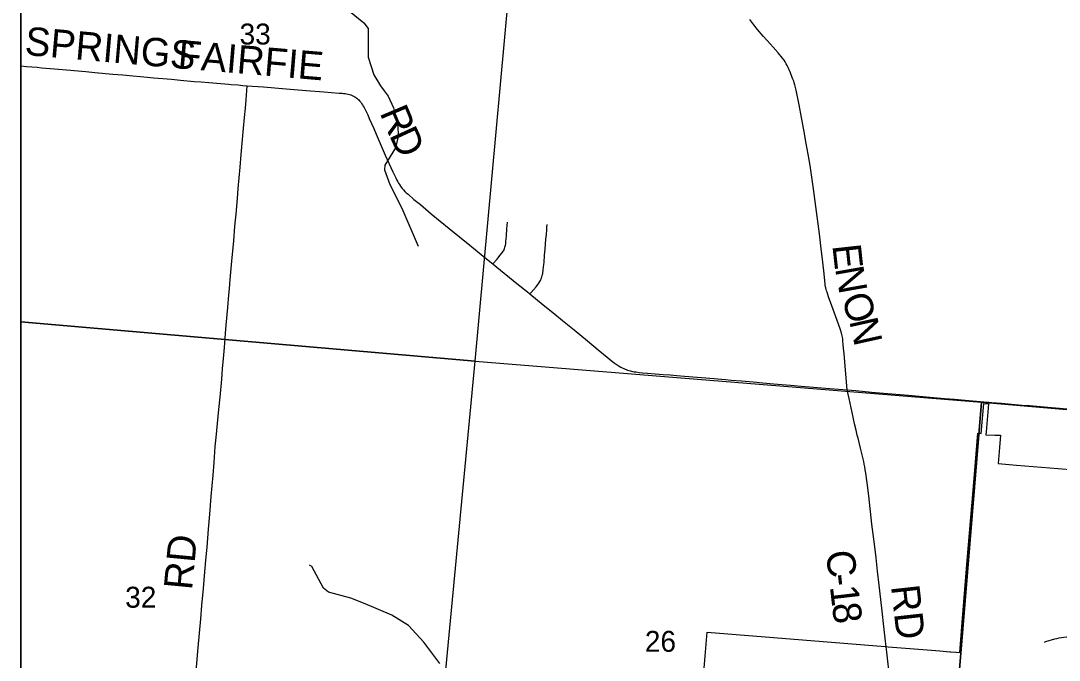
# Model space of a CAD drawing. Extents: x -1.4 to 35.4, y 0 to 22.
# Drawn here: x 17.06 to 19.136, y 17.381 to 18.66 of the extents above; entities that cross this region are included whole.
import ezdxf

# ---------------------------------------------------------------- set-up
doc = ezdxf.new("R2010")
doc.units = 0
for name, color, linetype in [('GM_X_City_Street', 7, 'Continuous'), ('GM_X_Corporation', 7, 'Continuous'), ('GM_X_County_Road', 7, 'Continuous'), ('GM_X_County_Road_Text', 7, 'Continuous'), ('GM_X_Minor_River', 7, 'Continuous'), ('GM_X_Section', 7, 'Continuous'), ('GM_X_Section_Text', 7, 'Continuous'), ('GM_X_Township_Road', 7, 'Continuous'), ('GM_X_Township_Road_Text', 7, 'Continuous'), ('SC_Scratch1', 7, 'Continuous'), ('SH_Border', 7, 'Continuous')]:
    doc.layers.add(name, color=color, linetype=linetype)

msp = doc.modelspace()

# ---------------------------------------------------------------- linework, layer by layer
at = {"layer": 'GM_X_City_Street'}
msp.add_lwpolyline([(19.1068, 17.417), (19.1097, 17.4178), (19.1274, 17.4232), (19.1316, 17.4243), (19.1363, 17.4253), (19.1408, 17.4261), (19.1456, 17.4268), (19.1515, 17.4272), (19.1527, 17.4273)], dxfattribs=at)
at = {"layer": 'GM_X_Corporation'}
msp.add_lwpolyline([(18.4168, 17.2527), (18.4324, 17.4366), (18.6233, 17.4213), (18.7882, 17.4081), (18.7899, 17.408), (18.7947, 17.4076), (18.89, 17.4), (18.8974, 17.3994), (18.898, 17.3993), (18.9178, 17.3976), (18.9199, 17.3974), (18.9296, 17.3966), (18.9304, 17.3965), (18.9376, 17.3959), (18.9425, 17.4558), (18.9532, 17.5879), (18.9618, 17.6896), (18.9624, 17.6967), (18.9664, 17.7453), (18.9691, 17.777), (18.974, 17.8351), (18.9804, 17.8347), (18.9855, 17.8943), (18.9949, 17.8935), (18.9902, 17.8379), (18.9897, 17.8317), (19.0076, 17.8312), (19.0192, 17.8309), (19.0172, 17.8066), (19.0146, 17.7742), (19.0512, 17.7712), (19.1345, 17.7644), (19.1976, 17.7593)], dxfattribs=at)
at = {"layer": 'GM_X_County_Road'}
for points in [[(17.0598, 19.0758), (17.0598, 18.058), (17.9683, 17.9793), (18.0613, 18.9927)], [(17.0598, 18.058), (17.0598, 17.0417), (17.8727, 16.9678), (17.9683, 17.9793)]]:
    msp.add_lwpolyline(points, close=True, dxfattribs=at)
for points in [[(18.7127, 17.9218), (18.709, 17.9613), (18.7061, 17.9947), (18.7053, 18.0047), (18.7045, 18.0133), (18.704, 18.0182), (18.7035, 18.0232), (18.7029, 18.0269), (18.7023, 18.03), (18.7018, 18.0327), (18.7012, 18.0349), (18.699, 18.0421), (18.6951, 18.0532), (18.6818, 18.09), (18.6752, 18.1079), (18.6736, 18.1127), (18.6721, 18.1173), (18.6713, 18.1201), (18.6706, 18.1228), (18.6699, 18.1256), (18.6693, 18.1281), (18.6687, 18.1312), (18.6683, 18.1341), (18.6677, 18.1396), (18.6662, 18.154), (18.6636, 18.177), (18.6599, 18.2097), (18.6568, 18.2337), (18.65, 18.2886), (18.645, 18.3237), (18.6381, 18.3704), (18.6344, 18.3931), (18.6306, 18.4145), (18.6254, 18.442), (18.6208, 18.467), (18.6161, 18.4921), (18.6101, 18.5213), (18.6089, 18.527), (18.6076, 18.5322), (18.6065, 18.5361), (18.6055, 18.5395), (18.604, 18.5435), (18.6027, 18.5471), (18.599, 18.5563), (18.5945, 18.5667), (18.5925, 18.5707), (18.5905, 18.5745), (18.5883, 18.5781), (18.5861, 18.5813), (18.5833, 18.5852), (18.5805, 18.5888), (18.5772, 18.5929), (18.5741, 18.5965), (18.5641, 18.6076), (18.5522, 18.6208), (18.5447, 18.6294), (18.533, 18.643), (18.5257, 18.6522), (18.518, 18.6627)], [(17.0598, 18.5701), (17.0713, 18.5691), (17.0929, 18.5672), (17.1015, 18.5665), (17.1275, 18.5643), (17.151, 18.5621), (17.19, 18.5589), (17.2079, 18.5571), (17.2438, 18.5537), (17.2636, 18.5519), (17.284, 18.5501), (17.2995, 18.5488), (17.3261, 18.5465), (17.3613, 18.5432), (17.3793, 18.5415), (17.4065, 18.5391), (17.4207, 18.5379), (17.4356, 18.5366), (17.4678, 18.534), (17.4752, 18.5334), (17.4808, 18.5331), (17.4944, 18.5319), (17.5036, 18.5311), (17.5128, 18.5302)], [(17.5128, 18.5302), (17.5451, 18.5279), (17.5903, 18.5241), (17.6306, 18.521), (17.6658, 18.518), (17.6968, 18.5156), (17.7023, 18.5152), (17.7054, 18.5149), (17.7085, 18.5145), (17.7113, 18.5141), (17.7143, 18.5134), (17.7169, 18.5128), (17.7198, 18.512), (17.7227, 18.5108), (17.7252, 18.5097), (17.7275, 18.5083), (17.73, 18.5066), (17.732, 18.5052), (17.7339, 18.5036), (17.7356, 18.5019), (17.7373, 18.5002), (17.7385, 18.4988), (17.7396, 18.4974), (17.7414, 18.4949), (17.7431, 18.4923), (17.7448, 18.4897), (17.7463, 18.487), (17.7484, 18.483), (17.7505, 18.4787), (17.7535, 18.4724), (17.7568, 18.4651), (17.7613, 18.4548), (17.7658, 18.4447), (17.7706, 18.4335), (17.7886, 18.3917), (17.8036, 18.358), (17.8095, 18.3458), (17.8118, 18.3414), (17.8135, 18.3383), (17.8151, 18.3353), (17.817, 18.3324), (17.8189, 18.3296), (17.8208, 18.3272), (17.8228, 18.3246), (17.8253, 18.3219), (17.8279, 18.319), (17.8308, 18.3163), (17.8343, 18.3131), (17.8461, 18.3029), (17.8591, 18.2924), (17.8805, 18.2743), (17.9167, 18.2449), (17.9373, 18.228), (17.9575, 18.2116), (17.9844, 18.1896), (18.0039, 18.1741)], [(18.0039, 18.1741), (18.0116, 18.1674), (18.0521, 18.1345), (18.073, 18.1178), (18.0781, 18.1137)], [(18.0781, 18.1137), (18.0932, 18.1013), (18.1075, 18.0894), (18.1235, 18.0765), (18.1432, 18.0604), (18.1665, 18.0417), (18.1929, 18.02), (18.2143, 18.002), (18.2325, 17.987), (18.2402, 17.9807), (18.2462, 17.9761), (18.2523, 17.9718), (18.2562, 17.9693), (18.2596, 17.9672), (18.2627, 17.9655), (18.2655, 17.9642), (18.2682, 17.9631), (18.2706, 17.9622), (18.2733, 17.9612), (18.2759, 17.9604), (18.2793, 17.9595), (18.2829, 17.9587), (18.2864, 17.958), (18.2901, 17.9575), (18.2966, 17.9567), (18.3032, 17.956), (18.3131, 17.9552), (18.3286, 17.9539), (18.3447, 17.9527), (18.3583, 17.9516), (18.3719, 17.9506), (18.3874, 17.9493), (18.4462, 17.9444), (18.453, 17.9438), (18.4691, 17.9422), (18.4802, 17.9412), (18.5013, 17.9396), (18.5242, 17.9375), (18.544, 17.9358), (18.565, 17.934), (18.5991, 17.9312), (18.6207, 17.9293), (18.6777, 17.9245), (18.6949, 17.9232), (18.7127, 17.9218)], [(18.7906, 17.4073), (18.7866, 17.4424), (18.7816, 17.485), (18.7764, 17.5307), (18.7732, 17.5591), (18.7701, 17.5856), (18.7681, 17.6022), (18.7657, 17.6232), (18.762, 17.6528), (18.7554, 17.7096), (18.7524, 17.7355), (18.7497, 17.7552), (18.7487, 17.7614), (18.7476, 17.7674), (18.7465, 17.7733), (18.7454, 17.7784), (18.7418, 17.7941), (18.7389, 17.8053), (18.7362, 17.8164), (18.7342, 17.8249), (18.7327, 17.8313), (18.7303, 17.8408), (18.7273, 17.8535), (18.7244, 17.8669), (18.7223, 17.8766), (18.7161, 17.9044), (18.7142, 17.913), (18.7127, 17.9218)], [(18.7127, 17.9218), (18.7297, 17.9204), (18.7613, 17.9174), (18.8015, 17.9138), (18.8349, 17.9108), (18.8777, 17.907), (18.9068, 17.9047), (18.9272, 17.9028), (18.9482, 17.901), (18.9857, 17.8976)], [(18.9857, 17.8976), (18.9905, 17.8973), (18.9957, 17.8969)], [(18.9957, 17.8969), (19.0018, 17.8964), (19.0211, 17.8948), (19.0619, 17.8914), (19.0768, 17.8902), (19.1208, 17.8867), (19.1604, 17.8832), (19.1864, 17.881), (19.2077, 17.8795)], [(18.8089, 17.2512), (18.8078, 17.2602), (18.8014, 17.3138), (18.798, 17.344), (18.7939, 17.3786), (18.7919, 17.3965), (18.7906, 17.4073)]]:
    msp.add_lwpolyline(points, dxfattribs=at)
at = {"layer": 'GM_X_Minor_River'}
for points in [[(17.7023, 18.6914), (17.7455, 18.656), (17.7543, 18.6452), (17.7547, 18.5875), (17.7661, 18.552), (17.7793, 18.5304), (17.7863, 18.5204), (17.7948, 18.5096), (17.8049, 18.4863), (17.8141, 18.4516), (17.8148, 18.4288), (17.8094, 18.4061), (17.7875, 18.3713), (17.7873, 18.3618), (17.7981, 18.3324), (17.8218, 18.2852), (17.8544, 18.2094)], [(17.7197, 17.5049), (17.6749, 17.5168), (17.6649, 17.525), (17.6419, 17.5684), (17.6374, 17.5711)], [(17.8977, 17.3741), (17.866, 17.4168), (17.8352, 17.4501), (17.8019, 17.4705), (17.7482, 17.4933), (17.7197, 17.5049)]]:
    msp.add_lwpolyline(points, dxfattribs=at)
at = {"layer": 'GM_X_Section'}
for points in [[(18.9811, 17.8973), (18.8977, 16.8845), (17.8727, 16.9678), (17.9683, 17.9793)], [(20.0033, 17.8091), (19.9161, 16.7998), (18.8977, 16.8845), (18.9811, 17.8973)]]:
    msp.add_lwpolyline(points, close=True, dxfattribs=at)
at = {"layer": 'GM_X_Township_Road'}
for points in [[(17.4106, 17.3588), (17.4148, 17.4058), (17.4198, 17.4634), (17.422, 17.49), (17.4249, 17.524), (17.4279, 17.5574), (17.4306, 17.5877), (17.4323, 17.6069), (17.4354, 17.6428), (17.4381, 17.6731), (17.4407, 17.7084), (17.4446, 17.7511), (17.4465, 17.7765), (17.4486, 17.8086), (17.4504, 17.8265), (17.456, 17.8827), (17.4584, 17.9068), (17.4616, 17.9433), (17.4634, 17.9638), (17.465, 17.9842), (17.4669, 18.0065), (17.4692, 18.0343), (17.4706, 18.051), (17.4739, 18.0863), (17.4761, 18.1116), (17.4772, 18.1246), (17.4787, 18.1426), (17.4821, 18.1791), (17.4856, 18.2199), (17.4881, 18.249), (17.4904, 18.2731), (17.4931, 18.3046), (17.4948, 18.3244), (17.4986, 18.3671), (17.5007, 18.3925), (17.5034, 18.4228), (17.5054, 18.4457), (17.5074, 18.4667), (17.5091, 18.4852), (17.5106, 18.5022), (17.5128, 18.5302)], [(18.0039, 18.1741), (18.0123, 18.1835), (18.018, 18.1903), (18.0221, 18.1953), (18.0234, 18.1971), (18.0247, 18.199), (18.0256, 18.2007), (18.0264, 18.2024), (18.0273, 18.2045), (18.0281, 18.2072), (18.029, 18.211), (18.0295, 18.2142), (18.0297, 18.2163), (18.03, 18.2194), (18.0304, 18.2236), (18.0308, 18.2299), (18.032, 18.2443), (18.0326, 18.2509), (18.0333, 18.2575)], [(18.0781, 18.1137), (18.08, 18.1159), (18.0903, 18.1279), (18.0939, 18.1325), (18.0957, 18.1351), (18.0977, 18.1385), (18.0988, 18.1404), (18.0999, 18.1427), (18.1009, 18.145), (18.102, 18.1483), (18.1025, 18.15), (18.1031, 18.1526), (18.1035, 18.1546), (18.1045, 18.1616), (18.1058, 18.1725), (18.1063, 18.1769), (18.1074, 18.1911), (18.1084, 18.2031), (18.1101, 18.2231), (18.1109, 18.2324), (18.1117, 18.2423), (18.112, 18.2472), (18.1124, 18.2522), (18.1124, 18.2528)]]:
    msp.add_lwpolyline(points, dxfattribs=at)
at = {"layer": 'SC_Scratch1'}
msp.add_lwpolyline([(17.0598, 19.0785), (17.0598, 16.0235)], dxfattribs=at)
at = {"layer": 'SH_Border'}
msp.add_lwpolyline([(17.0598, 19.8546), (23.8598, 19.8546), (23.8598, 13.0546), (17.0598, 13.0546)], close=True, dxfattribs=at)

# ---------------------------------------------------------------- texts
at = {"layer": 'GM_X_County_Road_Text'}
for s, height, rotation, p in [('SPRINGS', 0.05682, 355.0012, (17.0664, 18.5922)), ('FAIRFIE', 0.05682, 355.1619, (17.3726, 18.5655)), ('R', 0.0568, 292.8901, (17.7769, 18.4764)), ('D', 0.0568, 294.6778, (17.7958, 18.4317)), ('E', 0.0568, 276.3085, (18.6827, 18.2108)), ('N', 0.0568, 280.0172, (18.688, 18.1646)), ('O', 0.0568, 290.2253, (18.6995, 18.1047)), ('N', 0.0568, 282.5288, (18.7163, 18.0597)), ('C', 0.0568, 276.5165, (18.6697, 17.5979)), ('-', 0.0568, 276.5349, (18.675, 17.5515)), ('RD', 0.05682, 276.3402, (18.8, 17.5287)), ('1', 0.0568, 276.6408, (18.6777, 17.5282)), ('8', 0.0568, 277.1836, (18.6818, 17.4929))]:
    msp.add_text(s, height=height, rotation=rotation, dxfattribs=at).set_placement(p)
at = {"layer": 'GM_X_Section_Text'}
for s, p in [('33', (17.4974, 18.6129)), ('32', (17.2686, 17.4858)), ('26', (18.3078, 17.3975))]:
    msp.add_text(s, height=0.04186, rotation=0, dxfattribs=at).set_placement(p)
at = {"layer": 'GM_X_Township_Road_Text'}
msp.add_text('RD', height=0.05682, rotation=84.5821, dxfattribs=at).set_placement((17.4022, 17.52))

doc.saveas('drawing.dxf')
